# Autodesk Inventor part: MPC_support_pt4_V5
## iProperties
Shininess: 64.0
Length Units: 11269
Angle Units: 11279
Time Units: 11290
Mass Units: 11283
Length Display Precision: 3
Angle Display Precision: 2
Compacted: True
Part Number: MPC_support_pt4_V5
Document SubType Name: Modeling
Created: 2004-08
Designer: John Blackburn
Manufacturer: Standard
Standards Organization: Custom
Material: Stainless Steel, Austenitic
Density: 0.0
Volumn: 0.0
Area: 0.0
PropertySet Name: Model Information
Control State: 0
Master: False
Checked Out: False
Author: John Blackburn
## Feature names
1. Extrusion1
2. Hole1
3. Hole2
4. Hole3
5. Chamfer1
6. Fillet1
7. Hole4
